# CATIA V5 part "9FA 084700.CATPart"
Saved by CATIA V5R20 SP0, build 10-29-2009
Part number: 9FA 084700
Revision: ANY
Definition: UNKNOWN
Nomenclature: 9FA 084700
Source: Unknown
Bounding box of the stored display mesh (mm): x -4 to 3.804, y -10 to 10, z -4 to 4
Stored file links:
  C:\Users\Utente\Desktop\IO LAVORO\3D X SITO CF\CUMSA\3D files FA\FA 084700\9FA 084700.CATPart

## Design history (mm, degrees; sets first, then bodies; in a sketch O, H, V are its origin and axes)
Body1 "Redondeo2" (main body)
  Solid1: solid without history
